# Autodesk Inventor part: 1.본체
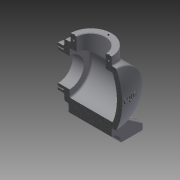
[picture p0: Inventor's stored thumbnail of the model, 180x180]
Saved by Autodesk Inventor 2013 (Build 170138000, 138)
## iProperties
Created: 2017-04
Part Number: 1.본체
Material: 일반
Document SubType Name: Modeling
Designer: Administrator
Density: 1 g/cm^3
Mass: 618.199 g
Surface Area: 1066.53 cm^2
Volume: 618.199 cm^3
Author: Administrator
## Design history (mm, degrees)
sketch "스케치1"
  geometry: L1 (-60, 0)-(60, 0); L2 (-60, 38)-(-48, 38); L3 (-48, 38)-(-48, 50); L4 (-48, 50)-(48.336, 50); L5 (-60, 38)-(-60, 0); L6 (-60, 0)-(60, 0); A1 r 113 centre (-53, 0) between (60, 0) and (48.336, 50); 2 further points
  constraints: 12 end point, 2 coincident, 2 parallel, 2 perpendicular, 2 point on circle, 1 centre point, 1 horizontal, 1 midpoint, 1 point on line
  dimensions: "d0" = 120 distance of L1.start L1.end; "d2" = 100 diameter of L4 L1; "d3" = 76 diameter of L2 L1; "d4" = 12 distance of L2.start L2.end; "d6" = 113 radius of A1; "d7" = 53 distance of point (0, 0) A1.centre
revolve "회전1" sketch "스케치1" stored, may be unused: angle "d9" = 90 deg
sketch "스케치2"
  geometry: L1 (60, -38)-(48, -38) reference; L2 (48, -38)-(48, -50) reference; L3 (48, -50)-(-48.336, -50) reference; L4 (-48.336, 50)-(48, 50) reference; L5 (48, 50)-(48, 38) reference; L6 (48, 38)-(60, 38) reference; L7 (60, 38)-(60, -38) reference; L8 (-41.916, -40)-(38, -40); L9 (38, -40)-(38, -27); L10 (60, 0)-(-60, 0); L11 (38, -27)-(60, -27); L12 (60, -27)-(60, 0); L13 (48, 50)-(48, -50) reference; A1 r 113 centre (53, 0) between (-48.336, 50) and (-48.336, -50) reference; A2 r 103 centre (53, 0) between (-50, 0) and (-41.916, -40); 1 further point
  constraints: 10 end point, 3 point on circle, 2 point on line, 1 centre point, 1 midpoint, 1 parallel, 1 perpendicular, 1 other
  dimensions: "d11" = 10 radial gap between concentric circles of A1 A2; "d12" = 80 diameter of L8 L10; "d13" = 54 diameter of L11 L10; "d107" = 108 distance from line of L10.end L13 (derived)
revolve "회전2" sketch "스케치2" stored, may be unused: angle "d14" = 90 deg
node "작업 평면1"
sketch "스케치4"
  geometry: L1 (40, 60)-(-40, 60); L2 (-40, 60)-(-40, -60); L3 (-40, -60)-(40, -60); L4 (40, -60)-(40, 60); L5 (-40, 60)-(40, -60); L6 (-48, -50)-(-48, 50) reference; 2 further points
  constraints: 10 end point, 2 parallel, 1 coincident, 1 horizontal, 1 midpoint, 1 perpendicular
  dimensions: "d16" = 120 distance of L1.end L2.end; "d18" = 80 distance of L2.end L3.end; "d19" = 8 distance between parallel lines of L2 L6
extrude "돌출1" join sketch "스케치4" distance "d20" = 10; taper "d21" = 0 deg
node "작업 평면2"
sketch "스케치5"
  geometry: L1 (-48, -50)-(-48, 50) reference; C1 r 38 at (2, 0); 1 further point
  constraints: 1 centre point, 1 horizontal alignment
  dimensions: "d23" = 76 diameter of C1; "d25" = 50 distance from line of C1.centre L1
extrude "돌출2" join sketch "스케치5" stored distance "d26" = 10; taper "d27" = 0 deg
sketch "스케치6"
  geometry: C1 r 38 at (0, 0) reference; C2 r 27 at (0, 0); 1 further point
  constraints: 1 centre point, 1 coincident
  dimensions: "d28" = 54 diameter of C2
extrude "돌출3" cut sketch "스케치6" stored distance "d30" = 10; taper "d31" = 0 deg
sketch "스케치7"
  geometry: L1 (0, 0)-(10, 0) reference; L2 (10, 120)-(10, 0) reference; L3 (0, 120)-(10, 120) reference; L4 (10, 120)-(36.899, 81.584); L5 (10, 0)-(36.899, 38.416); A1 r 50 centre (82, 60) between (36.899, 81.584) and (36.899, 38.416) reference; 1 further point
  constraints: 4 end point, 2 point on circle
  dimensions: "d32" = 55 deg angle of L3 L4; "d33" = 55 deg angle of L1 L5
extrude "돌출4" join sketch "스케치7" stored distance "d34" = 10; taper "d35" = 0 deg
sketch "스케치8"
  geometry: L1 (0, 120)-(0, 0) reference; A1 r 18 centre (0, 60) between (0, 78) and (0, 42); A2 r 18 centre (0, 60) between (0, 42) and (0, 78)
  constraints: 4 point on circle, 2 centre point, 2 point on line, 1 midpoint
  dimensions: "d36" = 36 diameter of A1
extrude "돌출5" cut sketch "스케치8" stored distance "d38" = 10; taper "d39" = 0 deg
sketch "스케치9" dims "d40" = 65
  geometry: L1 (0, 0)-(32.5, 0); C1 r 38 at (0, 0) reference; 1 further point
  constraints: 2 coincident, 2 end point, 1 horizontal, 1 horizontal alignment, 2 other
hole "구멍1" sketch "스케치9" at (32.5, 0) diameter "d42" = 3.242; stored, may be unused: countersink angle "d46" = 90 deg, drill point angle "d48" = 120 deg; dims "d43" = 8, "d44" = 4, "d45" = 2, "d47" = 10
sketch "스케치10" dims "d52" = 65
  geometry: L1 (0, 0)-(0, 32.5); C1 r 38 at (0, 0) reference; 2 further points
  constraints: 2 coincident, 2 end point, 1 vertical, 1 vertical alignment, 2 other
hole "구멍2" sketch "스케치10" at (0, 32.5) diameter "d54" = 3.242; stored, may be unused: countersink angle "d58" = 90 deg, drill point angle "d60" = 120 deg; dims "d55" = 8, "d56" = 4, "d57" = 2, "d59" = 10
sketch "스케치12"
  geometry: L1 (40, -18)-(40, -60) reference; L2 (-40, -60)-(-40, -18) reference; L3 (0, 0)-(60, 0); L4 (0, 0)-(0, 60); L5 (-40, 60)-(40, 60) reference; L6 (60, 38)-(60, -38) reference; L7 (40, 21.584)-(40, 60) reference; C1 r 4 at (20, -50); C2 r 4 at (20, 50); C3 r 4 at (-20, 50); C4 r 4 at (-20, -50)
  constraints: 4 centre point, 4 end point, 2 midpoint, 2 perpendicular, 2 symmetric about line, 1 equal radius, 2 other
  dimensions: "d68" = 8 diameter of C1; "d83" = 50 distance from line of C2.centre L3; "d84" = 20 distance from line of L1 C1.centre; "d85" = 20 distance from line of L7 C2.centre; "d86" = 50 distance from line of L3 C1.centre
extrude "돌출6" cut sketch "스케치12" distance "d69" = 8; taper "d70" = 0 deg
sketch "스케치16"
  geometry: L1 (-20, -66.125)-(60, -66.125) reference; L2 (60, -66.125)-(60, -110) reference; L3 (60, -110)-(-20, -110) reference; L4 (-20, -110)-(-20, -66.125) reference; L5 (60, -33.875)-(-20, -33.875) reference; L6 (-20, -33.875)-(-20, 10) reference; L7 (-20, 10)-(60, 10) reference; L8 (60, 10)-(60, -33.875) reference; L9 (8, 0)-(8, 10); L10 (-8, 0)-(-8, 10); L11 (20, -50)-(20, -33.875); L12 (60, -32)-(60, -68) reference; L13 (20, -50)-(60, -50); L14 (32, 0)-(32, 10); L15 (48, 0)-(48, 10); L16 (8, -100)-(8, -110); L17 (-8, -100)-(-8, -110); L18 (32, -100)-(32, -110); L19 (48, -100)-(48, -110); L20 (-8, 10)-(8, 10); L21 (32, 10)-(48, 10); L22 (48, -110)-(32, -110); L23 (8, -110)-(-8, -110); C1 r 4 at (0, 0) reference; C2 r 4 at (0, -100) reference; C3 r 4 at (40, 0) reference; C4 r 4 at (40, -100) reference; C5 r 4 at (0, 0) reference; A1 r 8 centre (0, 0) between (-8, 0) and (8, 0); A2 r 8 centre (40, 0) between (32, 0) and (48, 0); A3 r 8 centre (0, -100) between (8, -100) and (-8, -100); A4 r 8 centre (40, -100) between (48, -100) and (32, -100)
  constraints: 28 end point, 15 symmetric about line, 8 point on circle, 4 centre point, 3 parallel, 2 collinear, 2 midpoint, 2 point on line, 2 tangent, 1 coincident, 1 perpendicular, 3 other
  dimensions: "d87" = 16 diameter of A1
extrude "돌출10" cut sketch "스케치16" distance "d91" = 30; taper "d92" = 0 deg
chamfer "모따기1" distance "d97" = 1; stored, may be unused: second distance "d98" = 2, angle "d99" = 45 deg
fillet "모깎기1" dims "d100" = 3
fillet "모깎기2" dims "d101" = 3
fillet "모깎기3" dims "d102" = 3
fillet "모깎기5" dims "d104" = 3
node "작업 평면3"
sketch "스케치17"
  geometry: 2 further points
  constraints: 1 coincident, 1 other
feature "엠보싱1" sketch "스케치17" dims "d0" = 120, "d2" = 100, "d3" = 76, "d4" = 12, "d6" = 113, "d7" = 53, "d14" = 90 deg, "d105" = 0.5, "d106" = 0
node "솔리드1"
pattern_circular "원형 패턴1" dims angle "d50" = 360 deg
pattern_circular "원형 패턴2" dims angle "d62" = 360 deg
node "절단 모서리 투영1"
node "절단 모서리 투영4"
other parameters: "d15" = -82, "d22" = 147, "d93" = 0.5, "d94" = 2, "d95" = 0
